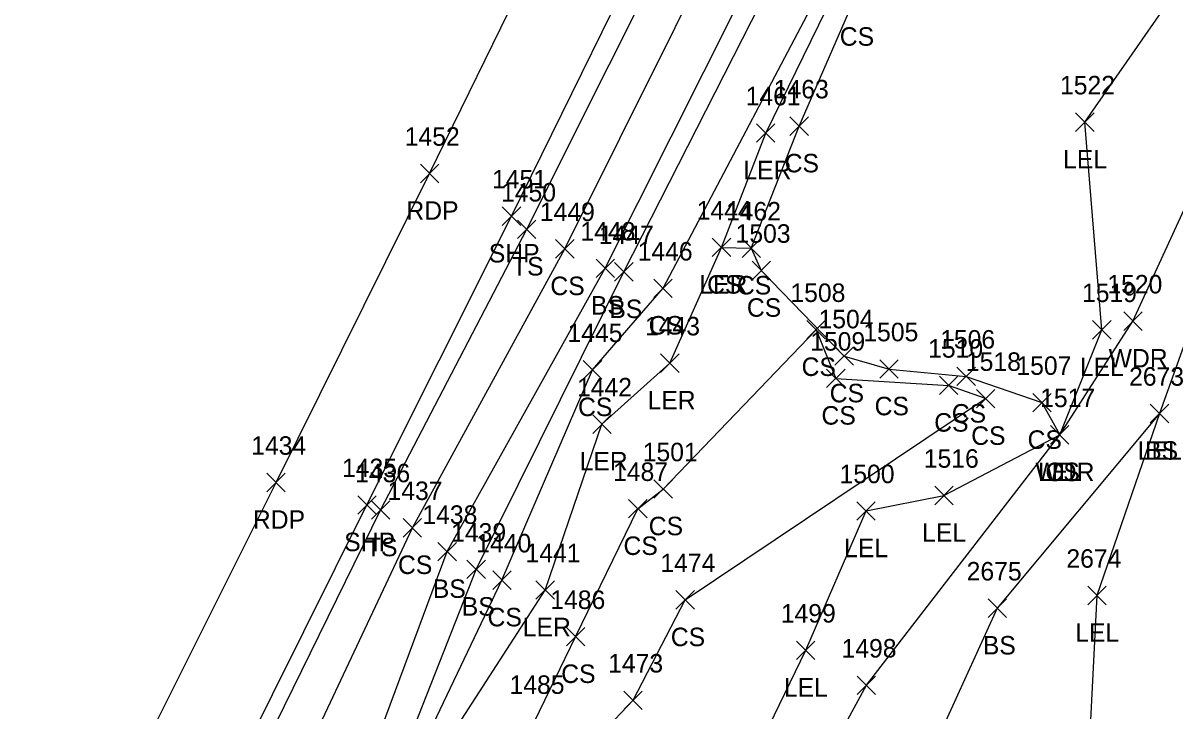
# Model space of a CAD drawing. Extents: x 1483143 to 1488182, y 802902 to 807581.
# Drawn here: x 1487503.2 to 1487627.8, y 805724.4 to 805798.7 of the extents above; entities that cross this region are included whole.
import ezdxf

# ---------------------------------------------------------------- set-up
doc = ezdxf.new("R2010")
doc.units = 0
for name, color, linetype in [('L_A', 7, 'Continuous'), ('L_I', 7, 'Continuous'), ('L_TIC', 7, 'Continuous'), ('LARO', 7, 'Continuous'), ('LAWA', 7, 'Continuous'), ('LELB', 7, 'Continuous'), ('P_A', 7, 'Continuous'), ('P_I', 7, 'Continuous'), ('P_TIC', 7, 'Continuous'), ('PET', 7, 'Continuous'), ('PSP', 7, 'Continuous')]:
    doc.layers.add(name, color=color, linetype=linetype)

msp = doc.modelspace()

# ---------------------------------------------------------------- linework, layer by layer
at = {"layer": 'L_TIC'}
for points in [[(1487586.14, 805786.59), (1487588.14, 805788.59)], [(1487588.14, 805786.59), (1487586.14, 805788.59)], [(1487617.06, 805787.02), (1487619.06, 805789.02)], [(1487619.06, 805787.02), (1487617.06, 805789.02)], [(1487582.53, 805785.84), (1487584.53, 805787.84)], [(1487584.53, 805785.84), (1487582.53, 805787.84)], [(1487556.67, 805775.44), (1487558.67, 805777.44)], [(1487558.67, 805775.44), (1487556.67, 805777.44)], [(1487577.75, 805773.48), (1487579.75, 805775.48)], [(1487579.75, 805773.48), (1487577.75, 805775.48)], [(1487577.75, 805773.48), (1487579.75, 805775.48)], [(1487579.75, 805773.48), (1487577.75, 805775.48)], [(1487560.79, 805773.32), (1487562.79, 805775.32)], [(1487562.79, 805773.32), (1487560.79, 805775.32)], [(1487580.97, 805773.39), (1487582.97, 805775.39)], [(1487582.97, 805773.39), (1487580.97, 805775.39)], [(1487580.97, 805773.39), (1487582.97, 805775.39)], [(1487582.97, 805773.39), (1487580.97, 805775.39)], [(1487565.17, 805771.22), (1487567.17, 805773.22)], [(1487567.17, 805771.22), (1487565.17, 805773.22)], [(1487567.17, 805770.84), (1487569.17, 805772.84)], [(1487569.17, 805770.84), (1487567.17, 805772.84)], [(1487582.05, 805770.98), (1487584.05, 805772.98)], [(1487584.05, 805770.98), (1487582.05, 805772.98)], [(1487571.42, 805769.06), (1487573.42, 805771.06)], [(1487573.42, 805769.06), (1487571.42, 805771.06)], [(1487622.26, 805765.5), (1487624.26, 805767.5)], [(1487624.26, 805765.5), (1487622.26, 805767.5)], [(1487587.97, 805764.58), (1487589.97, 805766.58)], [(1487589.97, 805764.58), (1487587.97, 805766.58)], [(1487618.89, 805764.57), (1487620.89, 805766.57)], [(1487620.89, 805764.57), (1487618.89, 805766.57)], [(1487591.01, 805761.73), (1487593.01, 805763.73)], [(1487593.01, 805761.73), (1487591.01, 805763.73)], [(1487563.78, 805760.24), (1487565.78, 805762.24)], [(1487565.78, 805760.24), (1487563.78, 805762.24)], [(1487572.16, 805760.97), (1487574.16, 805762.97)], [(1487574.16, 805760.97), (1487572.16, 805762.97)], [(1487595.87, 805760.33), (1487597.87, 805762.33)], [(1487597.87, 805760.33), (1487595.87, 805762.33)], [(1487590.12, 805759.32), (1487592.12, 805761.32)], [(1487592.12, 805759.32), (1487590.12, 805761.32)], [(1487602.32, 805758.56), (1487604.32, 805760.56)], [(1487604.32, 805758.56), (1487602.32, 805760.56)], [(1487604.22, 805759.54), (1487606.22, 805761.54)], [(1487606.22, 805759.54), (1487604.22, 805761.54)], [(1487606.32, 805757.13), (1487608.32, 805759.13)], [(1487608.32, 805757.13), (1487606.32, 805759.13)], [(1487612.42, 805756.7), (1487614.42, 805758.7)], [(1487614.42, 805756.7), (1487612.42, 805758.7)], [(1487625.14, 805755.53), (1487627.14, 805757.53)], [(1487627.14, 805755.53), (1487625.14, 805757.53)], [(1487625.14, 805755.53), (1487627.14, 805757.53)], [(1487627.14, 805755.53), (1487625.14, 805757.53)], [(1487564.81, 805754.37), (1487566.81, 805756.37)], [(1487566.81, 805754.37), (1487564.81, 805756.37)], [(1487614.34, 805753.21), (1487616.34, 805755.21)], [(1487616.34, 805753.21), (1487614.34, 805755.21)], [(1487614.34, 805753.21), (1487616.34, 805755.21)], [(1487616.34, 805753.21), (1487614.34, 805755.21)], [(1487614.34, 805753.21), (1487616.34, 805755.21)], [(1487616.34, 805753.21), (1487614.34, 805755.21)], [(1487571.43, 805747.36), (1487573.43, 805749.36)], [(1487573.43, 805747.36), (1487571.43, 805749.36)], [(1487601.81, 805746.66), (1487603.81, 805748.66)], [(1487603.81, 805746.66), (1487601.81, 805748.66)], [(1487540.86, 805745.09), (1487542.86, 805747.09)], [(1487542.86, 805745.09), (1487540.86, 805747.09)], [(1487568.7, 805745.23), (1487570.7, 805747.23)], [(1487570.7, 805745.23), (1487568.7, 805747.23)], [(1487593.38, 805744.99), (1487595.38, 805746.99)], [(1487595.38, 805744.99), (1487593.38, 805746.99)], [(1487544.3, 805743.17), (1487546.3, 805745.17)], [(1487546.3, 805743.17), (1487544.3, 805745.17)], [(1487548.07, 805740.59), (1487550.07, 805742.59)], [(1487550.07, 805740.59), (1487548.07, 805742.59)], [(1487551.2, 805738.67), (1487553.2, 805740.67)], [(1487553.2, 805738.67), (1487551.2, 805740.67)], [(1487553.99, 805737.51), (1487555.99, 805739.51)], [(1487555.99, 805737.51), (1487553.99, 805739.51)], [(1487558.66, 805736.44), (1487560.66, 805738.44)], [(1487560.66, 805736.44), (1487558.66, 805738.44)], [(1487573.82, 805735.37), (1487575.82, 805737.37)], [(1487575.82, 805735.37), (1487573.82, 805737.37)], [(1487618.37, 805735.85), (1487620.37, 805737.85)], [(1487620.37, 805735.85), (1487618.37, 805737.85)], [(1487607.58, 805734.47), (1487609.58, 805736.47)], [(1487609.58, 805734.47), (1487607.58, 805736.47)], [(1487561.96, 805731.39), (1487563.96, 805733.39)], [(1487563.96, 805731.39), (1487561.96, 805733.39)], [(1487586.86, 805729.92), (1487588.86, 805731.92)], [(1487588.86, 805729.92), (1487586.86, 805731.92)], [(1487593.42, 805726.14), (1487595.42, 805728.14)], [(1487595.42, 805726.14), (1487593.42, 805728.14)], [(1487568.17, 805724.52), (1487570.17, 805726.52)], [(1487570.17, 805724.52), (1487568.17, 805726.52)]]:
    msp.add_lwpolyline(points, dxfattribs=at)
at = {"layer": 'LARO'}
for points in [[(1487519.52, 805604.85), (1487528.65, 805619.18), (1487533.33, 805631.91), (1487543.2, 805654.53), (1487555.05, 805678.36), (1487574.29, 805702.91), (1487587.86, 805730.92), (1487594.38, 805745.99), (1487602.81, 805747.66), (1487615.34, 805754.21), (1487619.89, 805765.57), (1487618.06, 805788.02), (1487632.01, 805808.09), (1487647.52, 805827.2), (1487662.05, 805847.87), (1487673.84, 805865.59), (1487680.96, 805879.63), (1487690.31, 805890.08), (1487695.82, 805899.7), (1487708.05, 805917.66), (1487714.11, 805946.66), (1487707.45, 805965.6), (1487711.43, 805989.94)], [(1487515.16, 805650.67), (1487521.68, 805670.54), (1487529.04, 805683.79), (1487537.68, 805691.67), (1487539.17, 805698.49), (1487539.8, 805706.7), (1487559.66, 805737.44), (1487565.81, 805755.37), (1487573.16, 805761.97), (1487578.75, 805774.48), (1487583.53, 805786.84), (1487609.69, 805840.26), (1487624.13, 805853.53), (1487644.16, 805893.39), (1487661.53, 805944.93), (1487666.95, 805964.97), (1487680.31, 805984.75)], [(1487705.29, 805896.34), (1487695.87, 805891.2), (1487689.13, 805878.29), (1487689.57, 805859.67), (1487670.44, 805829.21), (1487659.71, 805823.79), (1487649.08, 805803.93), (1487638.97, 805785.42), (1487633.21, 805776.22), (1487626.14, 805756.53), (1487619.37, 805736.85), (1487617.73, 805704.95), (1487625.22, 805691.16), (1487634.64, 805682.02), (1487622.34, 805673.38), (1487621.2, 805638.86), (1487621.06, 805617.78)]]:
    msp.add_lwpolyline(points, dxfattribs=at)
at = {"layer": 'LAWA'}
msp.add_lwpolyline([(1487529.09, 805606.14), (1487539.28, 805632.42), (1487550.45, 805657.72), (1487555.05, 805678.36), (1487580.53, 805701.65), (1487594.42, 805727.14), (1487615.34, 805754.21), (1487623.26, 805766.5), (1487630.87, 805783.06), (1487637.96, 805804.22), (1487654.61, 805825.46), (1487661.73, 805840.49), (1487675.69, 805864.29), (1487683.26, 805876.52), (1487690.31, 805890.08), (1487698.57, 805894.98), (1487712.71, 805915.11), (1487715.76, 805935.97), (1487722.85, 805947.47), (1487721.66, 805955.35), (1487715.74, 805966.94), (1487726.15, 805982.46)], dxfattribs=at)
at = {"layer": 'LELB'}
for points in [[(1487406.66, 805485.41), (1487431.45, 805531.24), (1487454.84, 805575.74), (1487473.75, 805612.05), (1487489.43, 805642.37), (1487507.64, 805678.53), (1487524.82, 805711.39), (1487541.86, 805746.09), (1487557.67, 805776.44), (1487575.49, 805812.01), (1487597.52, 805857.93), (1487620.62, 805906.82), (1487641.85, 805951.94), (1487662.18, 805996.35), (1487684.09, 806043.93), (1487694.42, 806066.95), (1487726.58, 806140.7), (1487745.85, 806185.55), (1487769.04, 806237.65), (1487788.58, 806284.85), (1487808.3, 806333.26), (1487827.52, 806379.6), (1487850.09, 806437.73)], [(1487410.04, 805483.24), (1487436.07, 805529.53), (1487459.78, 805575.03), (1487477.42, 805609.67), (1487492.45, 805639.09), (1487509.86, 805677.27), (1487528.68, 805708.85), (1487545.3, 805744.17), (1487561.79, 805774.32), (1487579.7, 805810.21), (1487602.04, 805856.31), (1487624.97, 805905.57), (1487645.72, 805950.02), (1487667.21, 805993.1), (1487687.16, 806043.23), (1487699.2, 806065.16), (1487730.65, 806138.87), (1487749.96, 806183.58), (1487772.93, 806235.17), (1487792.36, 806283.08), (1487812.9, 806331.5), (1487831.61, 806378.23), (1487855.61, 806436.65)], [(1487413.83, 805481.53), (1487440.22, 805526.89), (1487464.36, 805572.85), (1487481.71, 805606.55), (1487496.63, 805636.25), (1487514.9, 805673.97), (1487535.8, 805705.94), (1487549.07, 805741.59), (1487566.17, 805772.22), (1487583.99, 805807.69), (1487605.26, 805855.28), (1487629.33, 805903.01), (1487650.26, 805948.76), (1487670.48, 805991.25), (1487690.28, 806041.74), (1487702.22, 806061.37), (1487704.47, 806066.39), (1487735.28, 806136.71), (1487754, 806182.42), (1487776.55, 806233.47), (1487796.75, 806281.41), (1487816.88, 806330.25), (1487835.19, 806376.59), (1487859.78, 806434.97)], [(1487417, 805480.8), (1487442.28, 805525.8), (1487466.47, 805571.82), (1487483.84, 805604.86), (1487498.25, 805635.76), (1487518.24, 805671.86), (1487538.47, 805704.77), (1487552.2, 805739.67), (1487568.17, 805771.84), (1487585.97, 805806.76), (1487609.39, 805853.47), (1487632.34, 805900.81), (1487653.02, 805947.32), (1487672.59, 805990.01), (1487694.92, 806039.27), (1487707.45, 806059.25), (1487710.05, 806064.3), (1487737.97, 806135.43), (1487757.4, 806181.42), (1487778.76, 806231.94), (1487799.97, 806279.97), (1487818.92, 806329.91), (1487837.5, 806376), (1487863.45, 806433.38)], [(1487539.8, 805706.7), (1487554.99, 805738.51), (1487564.78, 805761.24), (1487572.42, 805770.06), (1487590.42, 805804.18), (1487613.31, 805851.36), (1487639.64, 805896.3), (1487657.07, 805945.9), (1487666.95, 805964.97), (1487675.89, 805987.99), (1487698.82, 806037.9), (1487713.56, 806059.8), (1487740.03, 806134.78), (1487759.8, 806179.98), (1487782.43, 806230.23), (1487804.48, 806278.55), (1487821.45, 806329.34), (1487839.66, 806374.66), (1487865.87, 806433.14)], [(1487578.75, 805774.48), (1487581.97, 805774.39), (1487587.14, 805787.59), (1487593.1, 805801.28), (1487606.99, 805818.57), (1487613.06, 805830.36), (1487622.23, 805837.57), (1487633.56, 805844.35), (1487644.82, 805850.87), (1487647.66, 805852.57)], [(1487581.97, 805774.39), (1487583.05, 805771.98), (1487592.01, 805762.73), (1487596.87, 805761.33), (1487605.22, 805760.54), (1487613.42, 805757.7), (1487615.34, 805754.21)], [(1487428.48, 805479.23), (1487445.24, 805504.83), (1487451, 805517.25), (1487457.88, 805528.42), (1487471.74, 805554.31), (1487483.64, 805581.5), (1487492.13, 805596.22), (1487504.57, 805614.88), (1487515.61, 805636.44), (1487523.33, 805664.03), (1487527.1, 805668), (1487534.05, 805680.73), (1487538.75, 805686.85), (1487544.76, 805692.45), (1487548.74, 805693.28), (1487553.89, 805708.06), (1487558.5, 805723.21), (1487562.96, 805732.39), (1487569.7, 805746.23), (1487572.43, 805748.36), (1487588.97, 805765.58), (1487591.12, 805760.32), (1487603.32, 805759.56)], [(1487607.32, 805758.13), (1487603.32, 805759.56)], [(1487438.06, 805486.56), (1487449.51, 805502.69), (1487463.77, 805527.56), (1487473.75, 805548.89), (1487480.23, 805555.64), (1487489.68, 805553.31), (1487531.36, 805654.66), (1487538.66, 805667.76), (1487544.44, 805685.95), (1487547.35, 805690.53), (1487553.51, 805690.65), (1487551.83, 805696.06), (1487556.39, 805700.08), (1487558.02, 805713.74), (1487569.17, 805725.52), (1487574.82, 805736.37), (1487607.32, 805758.13)], [(1487626.14, 805756.53), (1487608.58, 805735.47), (1487598.51, 805713.44), (1487583.01, 805692.22), (1487563.99, 805676.49), (1487562.34, 805650.68)]]:
    msp.add_lwpolyline(points, dxfattribs=at)
at = {"layer": 'P_TIC'}
for points in [[(1487546.16, 805781.47), (1487548.16, 805783.47)], [(1487548.16, 805781.47), (1487546.16, 805783.47)], [(1487555.03, 805776.85), (1487557.03, 805778.85)], [(1487557.03, 805776.85), (1487555.03, 805778.85)], [(1487529.55, 805748.06), (1487531.55, 805750.06)], [(1487531.55, 805748.06), (1487529.55, 805750.06)], [(1487539.38, 805745.64), (1487541.38, 805747.64)], [(1487541.38, 805745.64), (1487539.38, 805747.64)]]:
    msp.add_lwpolyline(points, dxfattribs=at)
at = {"layer": 'PET'}
msp.add_lwpolyline([(1487396.33, 805490.41), (1487421.9, 805537.94), (1487444.13, 805580.16), (1487464.29, 805618.83), (1487479.8, 805648.39), (1487498.08, 805684.27), (1487514.57, 805717.15), (1487530.55, 805749.06), (1487547.16, 805782.47), (1487564.33, 805817.54), (1487585.71, 805863.32), (1487608.89, 805911.38), (1487630.35, 805956.68), (1487651.22, 806001.25), (1487672.63, 806048.33), (1487683.65, 806072.29), (1487715.61, 806144.47), (1487735.35, 806190.47), (1487757.48, 806241.03), (1487777.65, 806289.15), (1487798.25, 806337.46), (1487817.05, 806384.04), (1487839.67, 806441.4)], dxfattribs=at)
at = {"layer": 'PSP'}
msp.add_lwpolyline([(1487405.03, 805486.21), (1487429.8, 805532.42), (1487452.92, 805576.31), (1487472.37, 805613.24), (1487487.86, 805643.29), (1487506.35, 805679.4), (1487523.34, 805712.45), (1487540.38, 805746.64), (1487556.03, 805777.85), (1487573.44, 805813.27), (1487595.34, 805859.04), (1487618.37, 805906.67), (1487640.09, 805952.42), (1487660.18, 805997.21), (1487682.38, 806044.71), (1487693.04, 806068.56), (1487725.12, 806141.19), (1487744.39, 806185.87), (1487766.81, 806238.55), (1487786.8, 806285.64), (1487806.77, 806333.93), (1487825.55, 806380.21), (1487847.81, 806437.56)], dxfattribs=at)

# ---------------------------------------------------------------- texts
at = {"layer": 'L_A'}
for s, p in [('CS', (1487591.54, 805796.28)), ('CS', (1487585.58, 805782.59)), ('LEL', (1487615.7, 805783.02)), ('LER', (1487581.11, 805781.84)), ('TS', (1487556.08, 805771.44)), ('CS', (1487560.23, 805769.32)), ('LER', (1487576.34, 805769.48)), ('CS', (1487577.19, 805769.48)), ('CS', (1487580.41, 805769.39)), ('CS', (1487580.41, 805769.39)), ('BS', (1487564.61, 805767.22)), ('BS', (1487566.61, 805766.84)), ('CS', (1487581.49, 805766.98)), ('CS', (1487570.86, 805765.06)), ('WDR', (1487620.63, 805761.5)), ('CS', (1487587.41, 805760.58)), ('LEL', (1487617.52, 805760.57)), ('CS', (1487590.45, 805757.73)), ('CS', (1487563.22, 805756.24)), ('LER', (1487570.74, 805756.97)), ('CS', (1487595.31, 805756.33)), ('CS', (1487589.56, 805755.32)), ('CS', (1487603.66, 805755.54)), ('CS', (1487601.76, 805754.56)), ('CS', (1487605.76, 805753.13)), ('CS', (1487611.86, 805752.7)), ('LEL', (1487623.78, 805751.53)), ('BS', (1487624.58, 805751.53)), ('LER', (1487563.39, 805750.37)), ('WDR', (1487612.71, 805749.21)), ('LEL', (1487612.98, 805749.21)), ('CS', (1487613.79, 805749.21)), ('CS', (1487570.87, 805743.36)), ('LEL', (1487600.45, 805742.66)), ('TS', (1487540.27, 805741.09)), ('CS', (1487568.14, 805741.23)), ('LEL', (1487592.01, 805740.99)), ('CS', (1487543.74, 805739.17)), ('BS', (1487547.51, 805736.59)), ('BS', (1487550.64, 805734.67)), ('CS', (1487553.43, 805733.51)), ('LER', (1487557.24, 805732.44)), ('CS', (1487573.26, 805731.37)), ('LEL', (1487617.01, 805731.85)), ('BS', (1487607.02, 805730.47)), ('CS', (1487561.4, 805727.39)), ('LEL', (1487585.49, 805725.92))]:
    msp.add_text(s, height=2, dxfattribs=at).set_placement(p)
at = {"layer": 'L_I'}
for s, p in [('1522', (1487615.37, 805791.02)), ('1461', (1487581.36, 805789.84)), ('1463', (1487584.4, 805790.59)), ('1450', (1487554.89, 805779.44)), ('1449', (1487559.09, 805777.32)), ('1444', (1487576.06, 805777.48)), ('1444', (1487576.06, 805777.48)), ('1462', (1487579.23, 805777.39)), ('1462', (1487579.23, 805777.39)), ('1448', (1487563.48, 805775.22)), ('1447', (1487565.47, 805774.84)), ('1503', (1487580.27, 805774.98)), ('1446', (1487569.67, 805773.06)), ('1508', (1487586.2, 805768.58)), ('1519', (1487617.75, 805768.57)), ('1520', (1487620.49, 805769.5)), ('1443', (1487570.47, 805764.97)), ('1504', (1487589.24, 805765.73)), ('1445', (1487562.08, 805764.24)), ('1505', (1487594.09, 805764.33)), ('1506', (1487602.4, 805763.54)), ('1509', (1487588.34, 805763.32)), ('1510', (1487601.1, 805762.56)), ('1518', (1487605.19, 805761.13)), ('1507', (1487610.65, 805760.7)), ('2673', (1487622.84, 805759.53)), ('2673', (1487622.84, 805759.53)), ('1442', (1487563.11, 805758.37)), ('1517', (1487613.22, 805757.21)), ('1517', (1487613.22, 805757.21)), ('1517', (1487613.22, 805757.21)), ('1501', (1487570.22, 805751.36)), ('1516', (1487600.63, 805750.66)), ('1436', (1487539.11, 805749.09)), ('1487', (1487567.01, 805749.23)), ('1500', (1487591.52, 805748.99)), ('1437', (1487542.61, 805747.17)), ('1438', (1487546.38, 805744.59)), ('1439', (1487549.49, 805742.67)), ('1440', (1487552.21, 805741.51)), ('1441', (1487557.54, 805740.44)), ('2674', (1487616.06, 805739.85)), ('1474', (1487572.13, 805739.37)), ('2675', (1487605.27, 805738.47)), ('1486', (1487560.22, 805735.39)), ('1499', (1487585.16, 805733.92)), ('1498', (1487591.73, 805730.14)), ('1473', (1487566.48, 805728.52)), ('1485', (1487555.81, 805726.21))]:
    msp.add_text(s, height=2, dxfattribs=at).set_placement(p)
at = {"layer": 'P_A'}
for s, p in [('RDP', (1487544.65, 805777.47)), ('SHP', (1487553.57, 805772.85)), ('RDP', (1487528.04, 805744.06)), ('SHP', (1487537.92, 805741.64))]:
    msp.add_text(s, height=2, dxfattribs=at).set_placement(p)
at = {"layer": 'P_I'}
for s, p in [('1452', (1487544.47, 805785.47)), ('1451', (1487553.91, 805780.85)), ('1434', (1487527.86, 805752.06)), ('1435', (1487537.69, 805749.64))]:
    msp.add_text(s, height=2, dxfattribs=at).set_placement(p)

doc.saveas('drawing.dxf')
